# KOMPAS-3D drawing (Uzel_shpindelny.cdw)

Referenced files in C:\Мои документы\Studies\Станки-курсовик\: сборка-лист2.cdw
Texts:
  Курсовой проект
  Узел шпиндельный
  Третьякова
  125 1 126 1 127 1 128 0 50 1|SPDS|125 1 126 1 127 1 128 0 50 1
  129 1 130 1 131 1 132 0 50 1|SPDS|129 1 130 1 131 1 132 0 50 1
  Шестерни и подшипники обильно
  смазать смазкой, солидол "С"
  ГОСТ 4366-76
  Конусность
  Лит-Масса-Масштаб
  Материал-Предприятие
  Title Specification
  Body Specification ( left align )
  Body Specificaton ( centered )
  Поз.
  Кол.
  Приме-
  чание
  Таблица спецификации
  Курсовой проект-
  Узел
  шпиндельный
Dimensions and other numbers on the sheet: 42,4; 180; 7:24; 64; 75; 130; 128; 120; 100; 20; 105; 154; 41; 6; 1:1; 1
